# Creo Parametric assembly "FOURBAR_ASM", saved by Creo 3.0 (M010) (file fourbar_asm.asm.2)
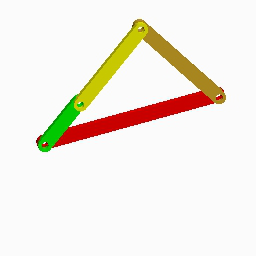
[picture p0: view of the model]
Units: millimeter Kilogram Sec (mmKs); MM, KILOGRAM, SECS

Created from: MMKS_ASM_DESIGN.ASM

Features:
  1. datum plane "ASM_RIGHT"
  2. datum plane "ASM_TOP"
  3. datum plane "ASM_FRONT"
  4. coordinate system
  5. component "BAR1"
  6. component "BAR2"
  7. component "BAR3"
  8. component "BAR4"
